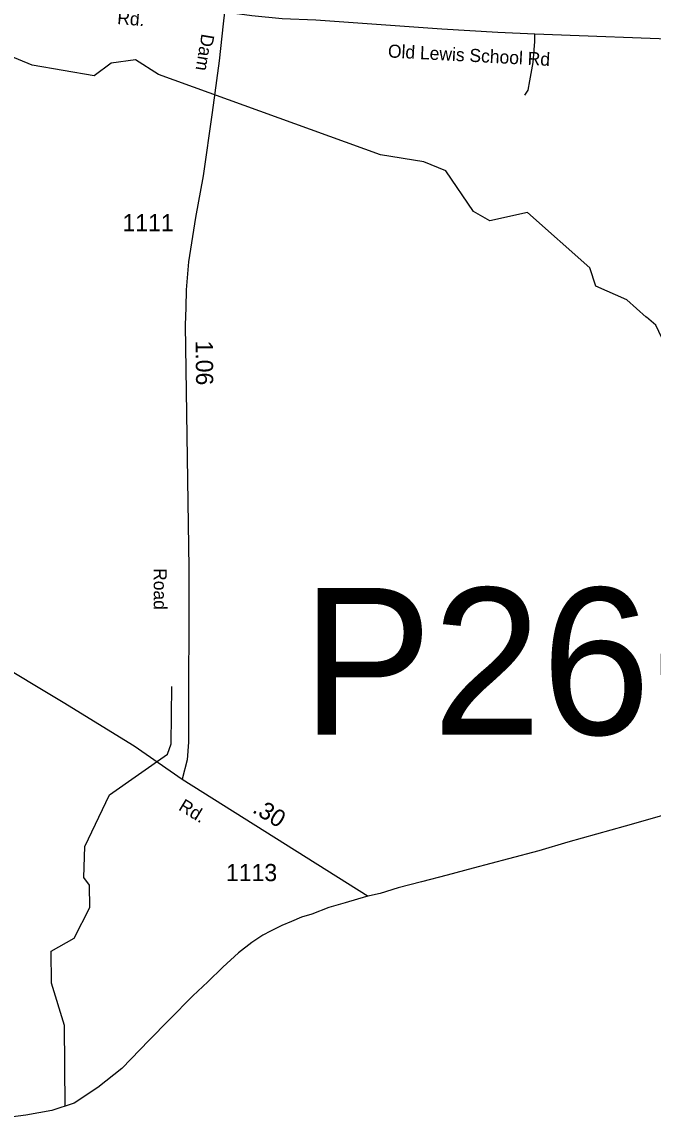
# Model space of a CAD drawing. Extents: x 2220236 to 2384410, y 720751 to 894131.
# Drawn here: x 2240958 to 2245544, y 723153 to 731129 of the extents above; entities that cross this region are included whole.
import ezdxf

# ---------------------------------------------------------------- set-up
doc = ezdxf.new("R2010")
doc.units = 0
for name, color, linetype in [('Exist Boundary Political CountyLine', 7, 'Continuous'), ('Exist Hydrographic Misc Water Feature', 7, 'Continuous'), ('Exist Road Non-System Type 51', 7, 'Continuous'), ('Exist Road Secondary Mileage Hundredths English Label', 7, 'Continuous'), ('Exist Road Secondary Structure Pipe Number Label', 7, 'Continuous'), ('Exist Road Secondary Type 51 Attributed', 7, 'Continuous'), ('Exist Road Secondary Type 51 Label', 7, 'Continuous'), ('Exist Road Secondary Type 51 Number Label', 7, 'Continuous')]:
    doc.layers.add(name, color=color, linetype=linetype)

msp = doc.modelspace()

# ---------------------------------------------------------------- linework, layer by layer
at = {"layer": 'Exist Boundary Political CountyLine'}
msp.add_lwpolyline([(2245674, 725376), (2245340.8, 725281.1), (2244925.7, 725165.6), (2244714.2, 725101.8), (2244494.8, 725046), (2244237.3, 724977.8), (2244047.6, 724926.2), (2243862, 724878.5), (2243692.4, 724833.1), (2243560.6, 724793.9), (2243462.9, 724771.1), (2243307.1, 724725.8), (2243189.4, 724690.8), (2243063.8, 724643.7), (2242990.1, 724621.2), (2242916.2, 724588.4), (2242846.4, 724559.9), (2242764.8, 724519.3), (2242709.2, 724488.8), (2242629.5, 724436.1), (2242532.1, 724361.4), (2242419, 724258.4), (2242309.9, 724151.6), (2242200.8, 724048.7), (2242028.2, 723873.4), (2241881.6, 723726.2), (2241683.4, 723519.3), (2241509.4, 723382), (2241338.8, 723268.2), (2241174.9, 723214.6), (2240987.5, 723181.2), (2240760.2, 723152.9)], dxfattribs=at)
at = {"layer": 'Exist Hydrographic Misc Water Feature'}
for p, q in [((2245495.9, 728982.5), (2245494.4, 728983.9)), ((2245512.6, 728967.8), (2245495.9, 728982.5))]:
    msp.add_line(p, q, dxfattribs=at)
for points in [[(2245494.4, 728983.9), (2245353.7, 729108.8), (2245127.5, 729208.5), (2245084.7, 729340.6), (2244631.5, 729743.5), (2244357.5, 729683.5), (2244240.7, 729751.5), (2244037.7, 730047.6), (2243878.5, 730113.1), (2243562.6, 730162.3), (2241949.6, 730746.4), (2241782.5, 730854.8), (2241607.6, 730828.9), (2241483.5, 730736.2), (2241032.6, 730814.4), (2240732.6, 730938.6), (2239747.5, 731119.5), (2239431.5, 731103), (2239290.4, 730984.6), (2239191.4, 730875.1), (2239089.5, 730099.8), (2238993.5, 729639.3), (2238968.5, 729616.9), (2238960.5, 729541.6)], [(2247310.8, 727254.8), (2247277.7, 727239.1), (2247175.6, 726545.8), (2247075.8, 726488.9), (2246966.7, 726563.2), (2247006.7, 726752.7), (2247011.6, 727179), (2246994.8, 727271.1), (2246624.6, 727734.7), (2246170.6, 728154), (2246028.5, 728229), (2245785.5, 728460.3), (2245564.7, 728924), (2245512.6, 728967.8)], [(2241271.3, 723246.1), (2241266.5, 723833), (2241172.4, 724140.1), (2241170.6, 724372.9), (2241336.5, 724467.9), (2241450.5, 724691.9), (2241449.5, 724852.7), (2241407.4, 724909.3), (2241414.6, 725135.4), (2241594.4, 725508.9), (2242016.4, 725805.4), (2242041.4, 725880.3), (2242046.6, 726296.7)]]:
    msp.add_lwpolyline(points, dxfattribs=at)
at = {"layer": 'Exist Road Non-System Type 51'}
msp.add_lwpolyline([(2244613, 730597), (2244635.8, 730633.1), (2244648.1, 730701.5), (2244672.8, 730834.4), (2244686.1, 730988.2), (2244686.1, 731039.5)], dxfattribs=at)
at = {"layer": 'Exist Road Secondary Type 51 Attributed'}
msp.add_line((2242122.6, 725624.2), (2243474.9, 724773.9), dxfattribs=at)
for points in [[(2242430, 731199.6), (2242421.3, 731114.4), (2242391.7, 730846.4), (2242339.5, 730470.7), (2242276.1, 730009.6), (2242218.7, 729708.6), (2242168.3, 729385), (2242150.9, 729181.5), (2242148.8, 729053.8), (2242145, 728925.3), (2242170, 727157.6), (2242168.7, 725892.2), (2242158.7, 725765.1), (2242122.6, 725624.2)], [(2245844.7, 730995.8), (2244686.1, 731039.5), (2244416.6, 731052.8), (2244008.6, 731075.6), (2243095, 731141.9), (2242849.9, 731151.5), (2242627.9, 731174.3), (2242430, 731199.6)], [(2239666.4, 726894.1), (2239907.4, 726837.8), (2240041.5, 726808.9), (2240207.8, 726764.3), (2240336.1, 726713.3), (2240478, 726639), (2240727.8, 726500.5), (2241258, 726185), (2241774.5, 725865.5), (2242122.6, 725624.2)]]:
    msp.add_lwpolyline(points, dxfattribs=at)

# ---------------------------------------------------------------- texts
at = {"layer": 'Exist Road Secondary Mileage Hundredths English Label'}
for s, rotation, p in [('1.06', 270.6652, (2242219.9, 728812.3)), ('.30', 328.59008, (2242626, 725386.8))]:
    msp.add_text(s, height=125, rotation=rotation, dxfattribs=at).set_placement(p)
at = {"layer": 'Exist Road Secondary Structure Pipe Number Label'}
msp.add_text('P266', height=1066.27, dxfattribs=at).set_placement((2242989.3, 725948))
at = {"layer": 'Exist Road Secondary Type 51 Label'}
for s, rotation, p in [('Rd.', 355.45064, (2241648.1, 731114.2)), ('Dam', 260.53095, (2242263.8, 731046.9)), ('Old Lewis School Rd', 356.96942, (2243615.8, 730871.5)), ('Road', 270.04621, (2241915.8, 727158.4)), ('Rd.', 328.59008, (2242089.5, 725404.4))]:
    msp.add_text(s, height=95, rotation=rotation, dxfattribs=at).set_placement(p)
at = {"layer": 'Exist Road Secondary Type 51 Number Label'}
for s, p in [('1111', (2241688.7, 729607)), ('1113', (2242440.8, 724882.6))]:
    msp.add_text(s, height=125, dxfattribs=at).set_placement(p)

doc.saveas('drawing.dxf')
